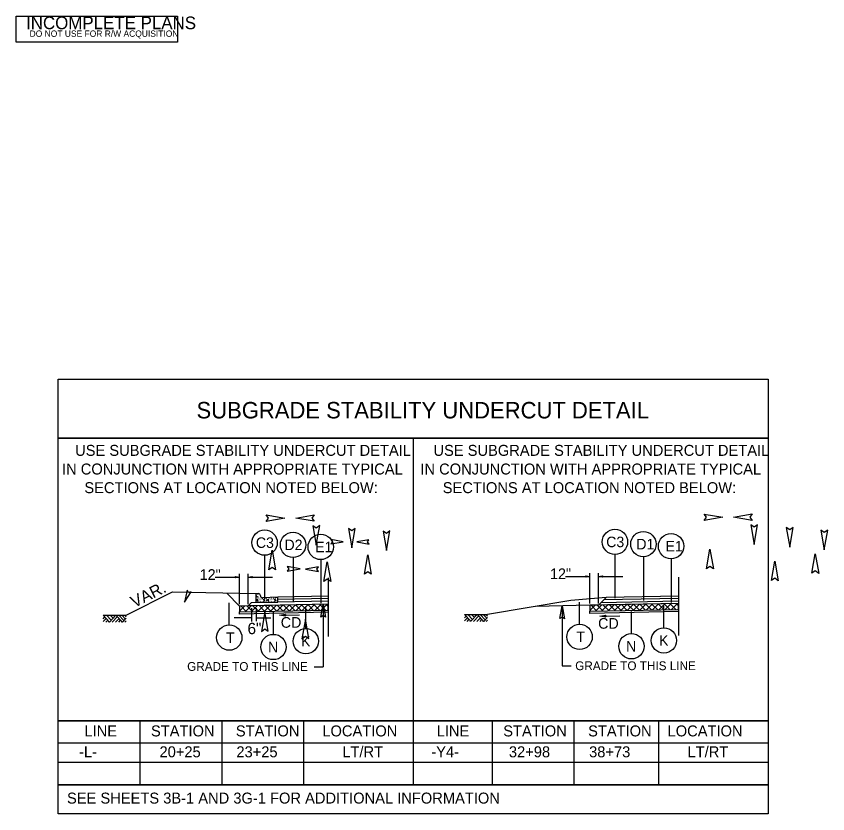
# Model space of a CAD drawing. Extents: x 1901718 to 1902220, y 193828 to 194187.
# Drawn here: x 1902146.1 to 1902220.1, y 194073.1 to 194145.8 of the extents above; entities that cross this region are included whole.
import ezdxf

# ---------------------------------------------------------------- set-up
doc = ezdxf.new("R2010")
doc.units = 0
for name, color, linetype in [('Old_Level_1', 7, 'Continuous'), ('Old_Level_11', 7, 'Continuous'), ('Old_Level_19', 7, 'Continuous'), ('Old_Level_42', 7, 'Continuous'), ('Prop Lane Arrow CELL', 7, 'Continuous'), ('Prop Terminator CELL', 7, 'Continuous'), ('Typical Berm CELL', 7, 'Continuous'), ('Typical Curb CELL', 7, 'Continuous'), ('Typical Detail Wedge1 CELL', 7, 'Continuous'), ('Typical Hinge Slope Arterial CELL', 7, 'Continuous'), ('Typical ID Circle CELL', 7, 'Continuous'), ('Typical Pavement Slope CELL', 7, 'Continuous'), ('Typical Terminator CELL', 7, 'Continuous'), ('Typical Text General CELL', 7, 'Continuous'), ('Typical Text ID Circle CELL', 7, 'Continuous')]:
    doc.layers.add(name, color=color, linetype=linetype)

msp = doc.modelspace()

# ---------------------------------------------------------------- linework, layer by layer
at = {"layer": 'Old_Level_1'}
for p, q in [((1902164.257, 194094.654), (1902166.477, 194094.654)), ((1902166.477, 194092.2), (1902166.477, 194094.954)), ((1902167.277, 194092.2), (1902167.277, 194094.954)), ((1902167.277, 194094.654), (1902169.495, 194094.654)), ((1902196.187, 194094.72), (1902198.407, 194094.72)), ((1902198.407, 194092.267), (1902198.407, 194095.021)), ((1902199.207, 194092.267), (1902199.207, 194095.021)), ((1902199.207, 194094.72), (1902201.425, 194094.72)), ((1902206.482, 194094.669), (1902206.482, 194089.331)), ((1902174.552, 194094.603), (1902174.552, 194089.264)), ((1902174.552, 194092.926), (1902169.989, 194092.835)), ((1902174.552, 194092.726), (1902169.989, 194092.635)), ((1902174.552, 194092.46), (1902169.989, 194092.368)), ((1902196.687, 194092.538), (1902189.073, 194091.269)), ((1902199.887, 194092.794), (1902196.687, 194092.538)), ((1902199.887, 194092.794), (1902199.207, 194092.114)), ((1902206.482, 194092.46), (1902199.411, 194092.318)), ((1902206.482, 194092.726), (1902199.683, 194092.59)), ((1902206.482, 194092.926), (1902199.887, 194092.794)), ((1902174.552, 194092.193), (1902166.477, 194092.031)), ((1902167.277, 194092.047), (1902166.477, 194092.031)), ((1902166.477, 194091.561), (1902166.957, 194092.041)), ((1902166.477, 194092.031), (1902166.477, 194091.498)), ((1902166.598, 194092.034), (1902167.121, 194091.511)), ((1902166.99, 194091.508), (1902167.534, 194092.052)), ((1902167.152, 194092.045), (1902167.675, 194091.522)), ((1902174.552, 194092.193), (1902167.277, 194092.047)), ((1902167.567, 194091.52), (1902168.111, 194092.064)), ((1902167.707, 194092.056), (1902168.23, 194091.533)), ((1902168.144, 194091.531), (1902168.688, 194092.076)), ((1902168.261, 194092.067), (1902168.784, 194091.544)), ((1902168.721, 194091.543), (1902169.266, 194092.087)), ((1902168.816, 194092.078), (1902169.339, 194091.555)), ((1902169.298, 194091.554), (1902169.843, 194092.099)), ((1902169.371, 194092.089), (1902169.894, 194091.566)), ((1902169.876, 194091.566), (1902170.42, 194092.11)), ((1902169.925, 194092.1), (1902170.448, 194091.577)), ((1902170.453, 194091.577), (1902170.997, 194092.122)), ((1902170.48, 194092.111), (1902171.003, 194091.588)), ((1902171.03, 194091.589), (1902171.574, 194092.133)), ((1902171.034, 194092.122), (1902171.557, 194091.599)), ((1902171.589, 194092.134), (1902172.112, 194091.611)), ((1902171.607, 194091.6), (1902172.152, 194092.145)), ((1902172.144, 194092.145), (1902172.667, 194091.622)), ((1902172.185, 194091.612), (1902172.729, 194092.156)), ((1902172.698, 194092.156), (1902173.221, 194091.633)), ((1902172.762, 194091.624), (1902173.306, 194092.168)), ((1902173.253, 194092.167), (1902173.776, 194091.644)), ((1902173.339, 194091.635), (1902173.883, 194092.179)), ((1902173.807, 194092.178), (1902174.33, 194091.655)), ((1902173.916, 194091.647), (1902174.461, 194092.191)), ((1902174.101, 194092.184), (1902174.101, 194086.478)), ((1902174.362, 194092.189), (1902174.552, 194091.999)), ((1902174.494, 194091.658), (1902174.552, 194091.717)), ((1902174.552, 194091.659), (1902174.552, 194092.193)), ((1902198.407, 194092.098), (1902193.45, 194091.999)), ((1902195.885, 194092.048), (1902195.885, 194086.584)), ((1902206.482, 194092.26), (1902198.407, 194092.098)), ((1902199.207, 194092.114), (1902198.407, 194092.098)), ((1902198.407, 194091.628), (1902198.886, 194092.108)), ((1902198.407, 194092.098), (1902198.407, 194091.565)), ((1902198.407, 194091.565), (1902206.482, 194091.726)), ((1902198.528, 194092.1), (1902199.051, 194091.577)), ((1902198.919, 194091.575), (1902199.464, 194092.119)), ((1902199.082, 194092.112), (1902199.605, 194091.589)), ((1902206.482, 194092.26), (1902199.207, 194092.114)), ((1902199.497, 194091.586), (1902200.041, 194092.131)), ((1902199.637, 194092.123), (1902200.16, 194091.6)), ((1902200.074, 194091.598), (1902200.618, 194092.142)), ((1902200.191, 194092.134), (1902200.714, 194091.611)), ((1902200.651, 194091.609), (1902201.195, 194092.154)), ((1902200.746, 194092.145), (1902201.269, 194091.622)), ((1902201.228, 194091.621), (1902201.773, 194092.165)), ((1902201.3, 194092.156), (1902201.824, 194091.633)), ((1902201.806, 194091.633), (1902202.35, 194092.177)), ((1902201.855, 194092.167), (1902202.378, 194091.644)), ((1902202.383, 194091.644), (1902202.927, 194092.188)), ((1902202.41, 194092.178), (1902202.933, 194091.655)), ((1902202.96, 194091.656), (1902203.504, 194092.2)), ((1902202.964, 194092.189), (1902203.487, 194091.666)), ((1902203.519, 194092.2), (1902204.042, 194091.677)), ((1902203.537, 194091.667), (1902204.082, 194092.212)), ((1902204.073, 194092.211), (1902204.596, 194091.688)), ((1902204.114, 194091.679), (1902204.659, 194092.223)), ((1902204.628, 194092.222), (1902205.151, 194091.699)), ((1902204.692, 194091.69), (1902205.236, 194092.235)), ((1902205.183, 194092.234), (1902205.706, 194091.711)), ((1902205.269, 194091.702), (1902205.813, 194092.246)), ((1902205.737, 194092.245), (1902206.26, 194091.722)), ((1902205.846, 194091.713), (1902206.39, 194092.258)), ((1902206.292, 194092.256), (1902206.482, 194092.066)), ((1902206.423, 194091.725), (1902206.482, 194091.783)), ((1902206.482, 194091.726), (1902206.482, 194092.26)), ((1902154.061, 194091.196), (1902154.64, 194090.573)), ((1902154.061, 194090.875), (1902154.21, 194091.035)), ((1902154.374, 194091.203), (1902154.8, 194090.744)), ((1902154.64, 194090.573), (1902155.225, 194091.202)), ((1902154.693, 194091.203), (1902154.959, 194090.915)), ((1902154.888, 194090.559), (1902155.357, 194091.061)), ((1902155.014, 194091.203), (1902155.12, 194091.088)), ((1902155.225, 194091.202), (1902155.818, 194090.565)), ((1902155.483, 194091.203), (1902155.947, 194090.704)), ((1902155.749, 194091.203), (1902156.08, 194090.847)), ((1902156.005, 194091.203), (1902156.141, 194091.056)), ((1902166.477, 194091.498), (1902174.552, 194091.659)), ((1902166.477, 194091.589), (1902166.566, 194091.5)), ((1902170.138, 194091.19), (1902171.959, 194091.234)), ((1902186.993, 194091.263), (1902187.572, 194090.64)), ((1902186.993, 194090.942), (1902187.142, 194091.102)), ((1902186.993, 194090.676), (1902187.266, 194090.969)), ((1902187.306, 194091.269), (1902187.732, 194090.811)), ((1902187.572, 194090.64), (1902188.157, 194091.269)), ((1902187.624, 194091.269), (1902187.89, 194090.982)), ((1902187.82, 194090.625), (1902188.289, 194091.128)), ((1902187.946, 194091.269), (1902188.052, 194091.155)), ((1902188.116, 194090.625), (1902188.436, 194090.969)), ((1902188.157, 194091.269), (1902188.75, 194090.632)), ((1902188.414, 194091.269), (1902188.878, 194090.771)), ((1902188.681, 194091.269), (1902189.012, 194090.914)), ((1902188.75, 194090.632), (1902189.073, 194090.98)), ((1902188.937, 194091.269), (1902189.073, 194091.123)), ((1902198.407, 194091.656), (1902198.496, 194091.566)), ((1902199.333, 194091.101), (1902201.154, 194091.144)), ((1902154.061, 194090.609), (1902154.335, 194090.902)), ((1902154.292, 194090.559), (1902154.473, 194090.753)), ((1902154.54, 194090.559), (1902154.597, 194090.619)), ((1902155.184, 194090.559), (1902155.504, 194090.902)), ((1902155.477, 194090.559), (1902155.651, 194090.745)), ((1902155.713, 194090.559), (1902155.768, 194090.618)), ((1902155.818, 194090.565), (1902156.141, 194090.913)), ((1902156.034, 194090.559), (1902156.141, 194090.673)), ((1902187.223, 194090.625), (1902187.405, 194090.82)), ((1902187.472, 194090.625), (1902187.529, 194090.686)), ((1902188.409, 194090.625), (1902188.582, 194090.812)), ((1902188.645, 194090.625), (1902188.7, 194090.685)), ((1902188.966, 194090.625), (1902189.073, 194090.74)), ((1902195.885, 194086.584), (1902196.705, 194086.584)), ((1902173.28, 194086.478), (1902174.101, 194086.478))]:
    msp.add_line(p, q, dxfattribs=at)
for points in [[(1902154.061, 194091.203), (1902156.141, 194091.203)], [(1902186.993, 194091.269), (1902189.073, 194091.269)]]:
    msp.add_lwpolyline(points, dxfattribs=at)
at = {"layer": 'Old_Level_11'}
for points in [[(1902173.901, 194091.02), (1902174.101, 194092.184), (1902174.308, 194091.014), (1902174.101, 194091.162)], [(1902195.684, 194090.884), (1902195.885, 194092.048), (1902196.092, 194090.878), (1902195.885, 194091.026)]]:
    msp.add_lwpolyline(points, close=True, dxfattribs=at)
at = {"layer": 'Old_Level_19'}
for p, q in [((1902182.315, 194107.337), (1902182.315, 194075.733)), ((1902182.315, 194105.294), (1902182.315, 194075.733)), ((1902157.409, 194081.583), (1902157.409, 194075.733)), ((1902164.863, 194081.583), (1902164.863, 194075.733)), ((1902172.316, 194081.583), (1902172.316, 194075.733)), ((1902189.513, 194081.583), (1902189.513, 194075.733)), ((1902196.966, 194081.583), (1902196.966, 194075.733)), ((1902204.675, 194081.583), (1902204.675, 194075.733)), ((1902214.674, 194079.539), (1902149.956, 194079.539)), ((1902157.409, 194079.539), (1902157.409, 194075.733)), ((1902164.863, 194079.539), (1902164.863, 194075.733)), ((1902172.316, 194079.539), (1902172.316, 194075.733)), ((1902189.513, 194079.539), (1902189.513, 194075.733)), ((1902196.966, 194079.539), (1902196.966, 194075.733)), ((1902204.675, 194079.539), (1902204.675, 194075.733)), ((1902214.674, 194077.777), (1902149.956, 194077.777)), ((1902214.674, 194075.733), (1902149.956, 194075.733))]:
    msp.add_line(p, q, dxfattribs=at)
for points in [[(1902149.956, 194112.695), (1902214.674, 194112.695), (1902214.674, 194107.337), (1902149.956, 194107.337)], [(1902149.956, 194107.337), (1902214.674, 194107.337), (1902214.674, 194081.583), (1902149.956, 194081.583)], [(1902149.956, 194075.733), (1902214.674, 194075.733), (1902214.674, 194073.102), (1902149.956, 194073.102)]]:
    msp.add_lwpolyline(points, close=True, dxfattribs=at)
msp.add_lwpolyline([(1902149.956, 194073.102), (1902149.956, 194081.583), (1902214.674, 194081.583), (1902214.674, 194073.102)], dxfattribs=at)
at = {"layer": 'Old_Level_42'}
msp.add_lwpolyline([(1902146.134, 194143.421), (1902146.134, 194145.771), (1902160.834, 194145.771), (1902160.834, 194143.421)], close=True, dxfattribs=at)
at = {"layer": 'Prop Lane Arrow CELL'}
for p, q in [((1902167.59, 194091.848), (1902167.59, 194090.617)), ((1902167.99, 194091.847), (1902167.99, 194090.649)), ((1902167.59, 194090.954), (1902165.997, 194090.954)), ((1902169.327, 194090.932), (1902167.99, 194090.932))]:
    msp.add_line(p, q, dxfattribs=at)
at = {"layer": 'Prop Terminator CELL'}
for points in [[(1902166.117, 194094.716), (1902166.477, 194094.654), (1902166.115, 194094.59), (1902166.161, 194094.654)], [(1902167.637, 194094.592), (1902167.277, 194094.654), (1902167.639, 194094.718), (1902167.593, 194094.654)], [(1902198.047, 194094.782), (1902198.407, 194094.72), (1902198.045, 194094.656), (1902198.091, 194094.72)], [(1902199.567, 194094.658), (1902199.207, 194094.72), (1902199.569, 194094.784), (1902199.523, 194094.72)], [(1902170.68, 194091.11), (1902170.138, 194091.19), (1902170.679, 194091.299), (1902170.612, 194091.201)], [(1902199.875, 194091.021), (1902199.333, 194091.101), (1902199.874, 194091.21), (1902199.807, 194091.112)]]:
    msp.add_lwpolyline(points, close=True, dxfattribs=at)
at = {"layer": 'Typical Berm CELL'}
msp.add_line((1902160.389, 194093.327), (1902167.99, 194093.168), dxfattribs=at)
at = {"layer": 'Typical Curb CELL'}
for p, q in [((1902167.99, 194092.368), (1902167.99, 194093.168)), ((1902167.99, 194093.168), (1902168.198, 194093.168)), ((1902168.019, 194092.866), (1902168.142, 194092.902)), ((1902168.129, 194092.829), (1902168.019, 194092.866)), ((1902168.12, 194092.611), (1902168.037, 194092.551)), ((1902168.037, 194092.551), (1902168.17, 194092.519)), ((1902168.17, 194092.519), (1902168.12, 194092.611)), ((1902168.142, 194092.902), (1902168.129, 194092.829)), ((1902168.39, 194092.968), (1902168.39, 194092.977)), ((1902169.989, 194092.835), (1902168.589, 194092.777)), ((1902168.713, 194092.656), (1902168.685, 194092.565)), ((1902168.685, 194092.565), (1902168.781, 194092.56)), ((1902168.781, 194092.56), (1902168.713, 194092.656)), ((1902169.119, 194092.611), (1902169.036, 194092.551)), ((1902169.036, 194092.551), (1902169.169, 194092.519)), ((1902169.169, 194092.519), (1902169.119, 194092.611)), ((1902169.712, 194092.656), (1902169.684, 194092.565)), ((1902169.684, 194092.565), (1902169.781, 194092.56)), ((1902169.781, 194092.56), (1902169.712, 194092.656)), ((1902169.989, 194092.368), (1902169.989, 194092.835)), ((1902167.99, 194092.368), (1902169.989, 194092.368))]:
    msp.add_line(p, q, dxfattribs=at)
for centre in [(1902168, 194093.08), (1902168.041, 194092.934), (1902168.119, 194092.716), (1902168.174, 194093.108), (1902168.215, 194092.756), (1902168.242, 194092.437), (1902168.357, 194092.624), (1902168.421, 194092.779), (1902168.43, 194092.478), (1902168.434, 194092.739), (1902168.457, 194092.601), (1902168.576, 194092.67), (1902168.599, 194092.751), (1902168.685, 194092.428), (1902168.754, 194092.72), (1902168.832, 194092.763), (1902168.854, 194092.56), (1902168.918, 194092.688), (1902168.931, 194092.524), (1902168.963, 194092.716), (1902168.977, 194092.638), (1902169.118, 194092.716), (1902169.214, 194092.756), (1902169.242, 194092.437), (1902169.356, 194092.624), (1902169.42, 194092.779), (1902169.429, 194092.478), (1902169.433, 194092.739), (1902169.456, 194092.601), (1902169.575, 194092.67), (1902169.598, 194092.751), (1902169.685, 194092.428), (1902169.717, 194092.802), (1902169.753, 194092.72), (1902169.831, 194092.788), (1902169.854, 194092.56), (1902169.918, 194092.688), (1902169.93, 194092.524), (1902169.962, 194092.716), (1902169.976, 194092.638), (1902168.105, 194092.405), (1902168.384, 194092.387), (1902168.521, 194092.41), (1902168.813, 194092.373), (1902168.981, 194092.391), (1902169.105, 194092.405), (1902169.383, 194092.387), (1902169.52, 194092.41), (1902169.812, 194092.373), (1902169.981, 194092.391)]:
    msp.add_circle(centre, 0.00642, dxfattribs=at)
for centre, start, end in [((1902168.198, 194092.977), 0, 90), ((1902168.581, 194092.968), 180, 272.38446)]:
    msp.add_arc(centre, 0.192, start, end, dxfattribs=at)
at = {"layer": 'Typical Detail Wedge1 CELL'}
for points in [[(1902198.407, 194091.565), (1902206.482, 194091.726), (1902206.482, 194091.526), (1902198.407, 194091.364)], [(1902166.477, 194091.498), (1902174.552, 194091.659), (1902174.552, 194091.459), (1902166.477, 194091.298)]]:
    msp.add_lwpolyline(points, close=True, dxfattribs=at)
at = {"layer": 'Typical Hinge Slope Arterial CELL'}
msp.add_line((1902156.141, 194091.203), (1902160.389, 194093.327), dxfattribs=at)
at = {"layer": 'Typical ID Circle CELL'}
for p, q in [((1902168.772, 194096.651), (1902168.772, 194092.675)), ((1902171.362, 194096.451), (1902171.362, 194092.475)), ((1902173.886, 194096.26), (1902173.886, 194092.283)), ((1902200.702, 194096.718), (1902200.702, 194092.741)), ((1902203.292, 194096.518), (1902203.292, 194092.541)), ((1902205.816, 194096.327), (1902205.816, 194092.35)), ((1902165.552, 194090.306), (1902165.552, 194092.313)), ((1902172.527, 194089.981), (1902172.527, 194091.989)), ((1902197.482, 194090.372), (1902197.482, 194092.38)), ((1902205.157, 194090.048), (1902205.157, 194092.055)), ((1902169.573, 194089.451), (1902169.573, 194091.458)), ((1902202.204, 194089.517), (1902202.204, 194091.525))]:
    msp.add_line(p, q, dxfattribs=at)
for centre in [(1902168.772, 194097.805), (1902171.362, 194097.605), (1902173.886, 194097.414), (1902200.702, 194097.872), (1902203.292, 194097.672), (1902205.816, 194097.481), (1902165.552, 194089.152), (1902197.482, 194089.218), (1902172.527, 194088.827), (1902202.204, 194088.363), (1902205.157, 194088.894), (1902169.573, 194088.297)]:
    msp.add_circle(centre, 1.154, dxfattribs=at)
at = {"layer": 'Typical Pavement Slope CELL'}
for p, q in [((1902166.477, 194092.031), (1902165.317, 194093.191)), ((1902167.277, 194092.047), (1902167.59, 194092.36)), ((1902167.59, 194092.36), (1902167.99, 194092.368))]:
    msp.add_line(p, q, dxfattribs=at)
at = {"layer": 'Typical Terminator CELL'}
for points in [[(1902168.928, 194100.33), (1902170.607, 194100.041), (1902168.919, 194099.743), (1902169.133, 194100.041)], [(1902173.285, 194099.752), (1902171.607, 194100.041), (1902173.295, 194100.34), (1902173.08, 194100.041)], [(1902208.84, 194100.414), (1902210.519, 194100.125), (1902208.831, 194099.826), (1902209.046, 194100.125)], [(1902213.197, 194099.836), (1902211.519, 194100.125), (1902213.207, 194100.423), (1902212.992, 194100.125)], [(1902173.169, 194099.349), (1902173.476, 194097.568), (1902173.792, 194099.359), (1902173.476, 194099.131)], [(1902176.407, 194099.099), (1902176.714, 194097.318), (1902177.03, 194099.109), (1902176.714, 194098.881)], [(1902213.081, 194099.432), (1902213.388, 194097.651), (1902213.704, 194099.442), (1902213.388, 194099.214)], [(1902216.319, 194099.182), (1902216.626, 194097.401), (1902216.942, 194099.192), (1902216.626, 194098.964)], [(1902179.562, 194098.86), (1902179.869, 194097.079), (1902180.185, 194098.87), (1902179.869, 194098.642)], [(1902219.474, 194098.943), (1902219.781, 194097.162), (1902220.097, 194098.953), (1902219.781, 194098.725)], [(1902174.815, 194097.688), (1902175.926, 194097.879), (1902174.809, 194098.077), (1902174.951, 194097.879)], [(1902178.285, 194098.07), (1902177.174, 194097.879), (1902178.291, 194097.682), (1902178.149, 194097.879)], [(1902169.145, 194095.335), (1902169.451, 194097.116), (1902169.768, 194095.325), (1902169.451, 194095.553)], [(1902209.057, 194095.418), (1902209.363, 194097.199), (1902209.68, 194095.408), (1902209.363, 194095.636)], [(1902177.862, 194094.929), (1902178.169, 194096.71), (1902178.486, 194094.919), (1902178.169, 194095.147)], [(1902214.959, 194094.349), (1902215.266, 194096.13), (1902215.582, 194094.339), (1902215.266, 194094.567)], [(1902218.651, 194095.013), (1902218.958, 194096.794), (1902219.274, 194095.003), (1902218.958, 194095.23)], [(1902170.826, 194095.216), (1902171.998, 194095.417), (1902170.82, 194095.626), (1902170.97, 194095.417)], [(1902173.67, 194095.592), (1902172.498, 194095.39), (1902173.676, 194095.181), (1902173.526, 194095.39)], [(1902174.171, 194094.266), (1902174.477, 194096.047), (1902174.794, 194094.256), (1902174.477, 194094.484)], [(1902161.717, 194093.469), (1902161.455, 194092.39), (1902162.07, 194093.322), (1902161.836, 194093.271)], [(1902169.105, 194089.726), (1902168.798, 194091.507), (1902168.482, 194089.716), (1902168.798, 194089.944)], [(1902172.797, 194089.063), (1902172.49, 194090.843), (1902172.173, 194089.053), (1902172.49, 194089.28)]]:
    msp.add_lwpolyline(points, close=True, dxfattribs=at)

# ---------------------------------------------------------------- texts
at = {"layer": 'Old_Level_1'}
for s, height, p in [('12"', 0.9735, (1902162.857, 194094.413)), ('12"', 0.9735, (1902194.787, 194094.479)), ('CD', 0.9735, (1902170.24, 194090.05)), ('CD', 0.9735, (1902199.167, 194089.961)), ('6" ', 1.04, (1902167.214, 194089.464))]:
    msp.add_text(s, height=height, dxfattribs=at).set_placement(p)
at = {"layer": 'Old_Level_11'}
for s, height, p in [('SUBGRADE STABILITY UNDERCUT DETAIL', 1.5, (1902162.565, 194109.124)), ('USE SUBGRADE STABILITY UNDERCUT DETAIL ', 1, (1902151.498, 194105.714)), ('USE SUBGRADE STABILITY UNDERCUT DETAIL ', 1, (1902184.157, 194105.714)), ('IN CONJUNCTION WITH APPROPRIATE TYPICAL ', 1, (1902150.306, 194104.014)), ('IN CONJUNCTION WITH APPROPRIATE TYPICAL ', 1, (1902182.966, 194104.014)), ('SECTIONS AT LOCATION NOTED BELOW:', 1, (1902152.344, 194102.314)), ('SECTIONS AT LOCATION NOTED BELOW:', 1, (1902185.004, 194102.314)), ('LINE', 1, (1902152.35, 194080.15)), ('STATION', 1, (1902158.415, 194080.15)), ('STATION', 1, (1902166.15, 194080.15)), ('LOCATION', 1, (1902174.032, 194080.15)), ('LINE', 1, (1902184.453, 194080.15)), ('STATION', 1, (1902190.518, 194080.15)), ('STATION', 1, (1902198.253, 194080.15)), ('LOCATION', 1, (1902205.497, 194080.15)), ('-L-', 1, (1902151.86, 194078.247)), ('20+25', 1, (1902159.191, 194078.247)), ('23+25', 1, (1902166.199, 194078.247)), ('LT/RT', 1, (1902175.852, 194078.247)), ('-Y4-', 1, (1902183.963, 194078.247)), ('32+98', 1, (1902191.036, 194078.247)), ('38+73', 1, (1902198.345, 194078.247)), ('LT/RT', 1, (1902207.317, 194078.247)), ('SEE SHEETS 3B-1 AND 3G-1 FOR ADDITIONAL INFORMATION', 1, (1902150.761, 194074.03))]:
    msp.add_text(s, height=height, dxfattribs=at).set_placement(p)
at = {"layer": 'Old_Level_42'}
for s, height, p in [('INCOMPLETE PLANS', 1.152, (1902147.029, 194144.591)), ('DO NOT USE FOR R/W ACQUISITION', 0.576, (1902147.354, 194143.896))]:
    msp.add_text(s, height=height, rotation=360, dxfattribs=at).set_placement(p)
at = {"layer": 'Typical Hinge Slope Arterial CELL'}
msp.add_text('VAR.', height=1.08, rotation=26.56505, dxfattribs=at).set_placement((1902156.896, 194091.842))
at = {"layer": 'Typical Text General CELL'}
for p in [(1902161.712, 194086.121), (1902197.08, 194086.188)]:
    msp.add_text('GRADE TO THIS LINE', height=0.8, dxfattribs=at).set_placement(p)
at = {"layer": 'Typical Text ID Circle CELL'}
for s, p in [('C3', (1902199.905, 194097.392)), ('C3', (1902167.976, 194097.325)), ('D2', (1902170.583, 194097.125)), ('E1', (1902173.377, 194096.934)), ('D1', (1902202.651, 194097.192)), ('E1', (1902205.307, 194097.001))]:
    msp.add_text(s, height=0.96, dxfattribs=at).set_placement(p)
for s, p in [('T', (1902165.246, 194088.672)), ('T', (1902197.175, 194088.738)), ('N', (1902169.082, 194087.817)), ('K', (1902172.092, 194088.347)), ('N', (1902201.713, 194087.883)), ('K', (1902204.723, 194088.414))]:
    msp.add_text(s, height=0.96, rotation=360, dxfattribs=at).set_placement(p)

doc.saveas('drawing.dxf')
